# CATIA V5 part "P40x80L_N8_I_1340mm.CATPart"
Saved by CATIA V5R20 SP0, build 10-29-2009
Part number: 80x40_X-Traeger
Nomenclature: P40x80L_N8_I
Source: Unknown
Bounding box of the stored display mesh (mm): x -25.6 to 54.4, y 0 to 40, z 0 to 1420
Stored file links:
  C:\Users\Andi\Desktop\Offene Projekte\Plasmacutter\Rahmen\P40x80L_N8_I_1340mm.CATPart
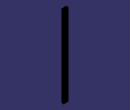
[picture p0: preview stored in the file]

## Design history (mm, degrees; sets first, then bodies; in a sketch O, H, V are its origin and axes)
Set1
  Sketch1 on face of Solid1, origin (0, 0, 1000), H (1, 0, 0), V (0, 1, 0)
    projected arc E1 centre (2, 37.5) radius 0.5 from (2, 38) to (1.5, 37.5) ccw from edge [face of Solid1 | face of Solid1]
    projected arc E2 centre (2, 35.5) radius 2.5 from (4.5, 35.5) to (2, 38) ccw from edge [face of Solid1 | face of Solid1]
    projected line E3 (4.5, 34.2924) -> (4.5, 35.5) from edge [face of Solid1 | face of Solid1]
    projected arc E4 centre (-0.5, 34.2924) radius 5 from (3.0355, 30.7569) to (4.5, 34.2924) ccw from edge [face of Solid1 | face of Solid1]
    projected line E5 (1.3431, 29.0645) -> (3.0355, 30.7569) from edge [face of Solid1 | face of Solid1]
    projected arc E6 centre (-2.1924, 32.6) radius 5 from (-2.1924, 27.6) to (1.3431, 29.0645) ccw from edge [face of Solid1 | face of Solid1]
    projected line E7 (-9.0076, 27.6) -> (-2.1924, 27.6) from edge [face of Solid1 | face of Solid1]
    projected arc E8 centre (-9.0076, 32.6) radius 5 from (-12.5431, 29.0645) to (-9.0076, 27.6) ccw from edge [face of Solid1 | face of Solid1]
    projected line E9 (-14.2355, 30.7569) -> (-12.5431, 29.0645) from edge [face of Solid1 | face of Solid1]
    projected arc E10 centre (-10.7, 34.2924) radius 5 from (-15.7, 34.2924) to (-14.2355, 30.7569) ccw from edge [face of Solid1 | face of Solid1]
    projected line E11 (-15.7, 35.5) -> (-15.7, 34.2924) from edge [face of Solid1 | face of Solid1]
    projected arc E12 centre (-13.2, 35.5) radius 2.5 from (-13.2, 38) to (-15.7, 35.5) ccw from edge [face of Solid1 | face of Solid1]
    projected arc E13 centre (-13.2, 37.5) radius 0.5 from (-12.7, 37.5) to (-13.2, 38) ccw from edge [face of Solid1 | face of Solid1]
    projected line E14 (-12.7, 35.85) -> (-12.7, 37.5) from edge [face of Solid1 | face of Solid1]
    projected arc E15 centre (-12.2, 35.85) radius 0.5 from (-12.7, 35.85) to (-12.2, 35.35) ccw from edge [face of Solid1 | face of Solid1]
    projected line E16 (-10.7, 35.35) -> (-12.2, 35.35) from edge [face of Solid1 | face of Solid1]
    projected arc E17 centre (-10.7, 36.35) radius 1 from (-10.7, 35.35) to (-9.7, 36.35) ccw from edge [face of Solid1 | face of Solid1]
    projected line E18 (-9.7, 38.5) -> (-9.7, 36.35) from edge [face of Solid1 | face of Solid1]
    projected arc E19 centre (-11.2, 38.5) radius 1.5 from (-9.7, 38.5) to (-11.2, 40) ccw from edge [face of Solid1 | face of Solid1]
    projected line E20 (-21.6, 40) -> (-11.2, 40) from edge [face of Solid1 | face of Solid1]
    projected arc E21 centre (-21.6, 36) radius 4 from (-21.6, 40) to (-25.6, 36) ccw from edge [face of Solid1 | face of Solid1]
    projected line E22 (-25.6, 25.6) -> (-25.6, 36) from edge [face of Solid1 | face of Solid1]
    projected arc E23 centre (-24.1, 25.6) radius 1.5 from (-25.6, 25.6) to (-24.1, 24.1) ccw from edge [face of Solid1 | face of Solid1]
    projected line E24 (-21.95, 24.1) -> (-24.1, 24.1) from edge [face of Solid1 | face of Solid1]
    projected arc E25 centre (-21.95, 25.1) radius 1 from (-21.95, 24.1) to (-20.95, 25.1) ccw from edge [face of Solid1 | face of Solid1]
    projected line E26 (-20.95, 26.6) -> (-20.95, 25.1) from edge [face of Solid1 | face of Solid1]
    projected arc E27 centre (-21.45, 26.6) radius 0.5 from (-20.95, 26.6) to (-21.45, 27.1) ccw from edge [face of Solid1 | face of Solid1]
    projected line E28 (-23.1, 27.1) -> (-21.45, 27.1) from edge [face of Solid1 | face of Solid1]
    projected arc E29 centre (-23.1, 27.6) radius 0.5 from (-23.6, 27.6) to (-23.1, 27.1) ccw from edge [face of Solid1 | face of Solid1]
    projected arc E30 centre (-21.1, 27.6) radius 2.5 from (-21.1, 30.1) to (-23.6, 27.6) ccw from edge [face of Solid1 | face of Solid1]
    projected line E31 (-19.8924, 30.1) -> (-21.1, 30.1) from edge [face of Solid1 | face of Solid1]
    projected arc E32 centre (-19.8924, 25.1) radius 5 from (-16.3569, 28.6355) to (-19.8924, 30.1) ccw from edge [face of Solid1 | face of Solid1]
    projected line E33 (-14.6645, 26.9431) -> (-16.3569, 28.6355) from edge [face of Solid1 | face of Solid1]
    projected arc E34 centre (-18.2, 23.4076) radius 5 from (-13.2, 23.4076) to (-14.6645, 26.9431) ccw from edge [face of Solid1 | face of Solid1]
    projected line E35 (-13.2, 16.5924) -> (-13.2, 23.4076) from edge [face of Solid1 | face of Solid1]
    projected arc E36 centre (-18.2, 16.5924) radius 5 from (-14.6645, 13.0569) to (-13.2, 16.5924) ccw from edge [face of Solid1 | face of Solid1]
    projected line E37 (-16.3569, 11.3645) -> (-14.6645, 13.0569) from edge [face of Solid1 | face of Solid1]
    projected arc E38 centre (-19.8924, 14.9) radius 5 from (-19.8924, 9.9) to (-16.3569, 11.3645) ccw from edge [face of Solid1 | face of Solid1]
    projected line E39 (-21.1, 9.9) -> (-19.8924, 9.9) from edge [face of Solid1 | face of Solid1]
    projected arc E40 centre (-21.1, 12.4) radius 2.5 from (-23.6, 12.4) to (-21.1, 9.9) ccw from edge [face of Solid1 | face of Solid1]
    projected arc E41 centre (-23.1, 12.4) radius 0.5 from (-23.1, 12.9) to (-23.6, 12.4) ccw from edge [face of Solid1 | face of Solid1]
    projected line E42 (-21.45, 12.9) -> (-23.1, 12.9) from edge [face of Solid1 | face of Solid1]
    projected arc E43 centre (-21.45, 13.4) radius 0.5 from (-21.45, 12.9) to (-20.95, 13.4) ccw from edge [face of Solid1 | face of Solid1]
    projected line E44 (-20.95, 14.9) -> (-20.95, 13.4) from edge [face of Solid1 | face of Solid1]
    projected arc E45 centre (-21.95, 14.9) radius 1 from (-20.95, 14.9) to (-21.95, 15.9) ccw from edge [face of Solid1 | face of Solid1]
    projected line E46 (-24.1, 15.9) -> (-21.95, 15.9) from edge [face of Solid1 | face of Solid1]
    projected arc E47 centre (-24.1, 14.4) radius 1.5 from (-24.1, 15.9) to (-25.6, 14.4) ccw from edge [face of Solid1 | face of Solid1]
    projected line E48 (-25.6, 4) -> (-25.6, 14.4) from edge [face of Solid1 | face of Solid1]
    projected arc E49 centre (-21.6, 4) radius 4 from (-25.6, 4) to (-21.6, 0) ccw from edge [face of Solid1 | face of Solid1]
    projected line E50 (-11.2, 0) -> (-21.6, 0) from edge [face of Solid1 | face of Solid1]
    projected arc E51 centre (-11.2, 1.5) radius 1.5 from (-11.2, 0) to (-9.7, 1.5) ccw from edge [face of Solid1 | face of Solid1]
    projected line E52 (-9.7, 3.65) -> (-9.7, 1.5) from edge [face of Solid1 | face of Solid1]
    projected arc E53 centre (-10.7, 3.65) radius 1 from (-9.7, 3.65) to (-10.7, 4.65) ccw from edge [face of Solid1 | face of Solid1]
    projected line E54 (-12.2, 4.65) -> (-10.7, 4.65) from edge [face of Solid1 | face of Solid1]
    projected arc E55 centre (-12.2, 4.15) radius 0.5 from (-12.2, 4.65) to (-12.7, 4.15) ccw from edge [face of Solid1 | face of Solid1]
    projected line E56 (-12.7, 2.5) -> (-12.7, 4.15) from edge [face of Solid1 | face of Solid1]
    projected arc E57 centre (-13.2, 2.5) radius 0.5 from (-13.2, 2) to (-12.7, 2.5) ccw from edge [face of Solid1 | face of Solid1]
    projected arc E58 centre (-13.2, 4.5) radius 2.5 from (-15.7, 4.5) to (-13.2, 2) ccw from edge [face of Solid1 | face of Solid1]
    projected line E59 (-15.7, 5.7076) -> (-15.7, 4.5) from edge [face of Solid1 | face of Solid1]
    projected arc E60 centre (-10.7, 5.7076) radius 5 from (-14.2355, 9.2431) to (-15.7, 5.7076) ccw from edge [face of Solid1 | face of Solid1]
    projected line E61 (-12.5431, 10.9355) -> (-14.2355, 9.2431) from edge [face of Solid1 | face of Solid1]
    projected arc E62 centre (-9.0076, 7.4) radius 5 from (-9.0076, 12.4) to (-12.5431, 10.9355) ccw from edge [face of Solid1 | face of Solid1]
    projected line E63 (-2.1924, 12.4) -> (-9.0076, 12.4) from edge [face of Solid1 | face of Solid1]
    projected arc E64 centre (-2.1924, 7.4) radius 5 from (1.3431, 10.9355) to (-2.1924, 12.4) ccw from edge [face of Solid1 | face of Solid1]
    projected line E65 (3.0355, 9.2431) -> (1.3431, 10.9355) from edge [face of Solid1 | face of Solid1]
    projected arc E66 centre (-0.5, 5.7076) radius 5 from (4.5, 5.7076) to (3.0355, 9.2431) ccw from edge [face of Solid1 | face of Solid1]
    projected line E67 (4.5, 4.5) -> (4.5, 5.7076) from edge [face of Solid1 | face of Solid1]
    projected arc E68 centre (2, 4.5) radius 2.5 from (2, 2) to (4.5, 4.5) ccw from edge [face of Solid1 | face of Solid1]
    projected arc E69 centre (2, 2.5) radius 0.5 from (1.5, 2.5) to (2, 2) ccw from edge [face of Solid1 | face of Solid1]
    projected line E70 (1.5, 4.15) -> (1.5, 2.5) from edge [face of Solid1 | face of Solid1]
    projected arc E71 centre (1, 4.15) radius 0.5 from (1.5, 4.15) to (1, 4.65) ccw from edge [face of Solid1 | face of Solid1]
    projected line E72 (-0.5, 4.65) -> (1, 4.65) from edge [face of Solid1 | face of Solid1]
    projected arc E73 centre (-0.5, 3.65) radius 1 from (-0.5, 4.65) to (-1.5, 3.65) ccw from edge [face of Solid1 | face of Solid1]
    projected line E74 (-1.5, 1.5) -> (-1.5, 3.65) from edge [face of Solid1 | face of Solid1]
    projected arc E75 centre (0, 1.5) radius 1.5 from (-1.5, 1.5) to (0, 0) ccw from edge [face of Solid1 | face of Solid1]
    projected line E76 (28.8, 0) -> (0, 0) from edge [face of Solid1 | face of Solid1]
    projected arc E77 centre (28.8, 1.5) radius 1.5 from (28.8, 0) to (30.3, 1.5) ccw from edge [face of Solid1 | face of Solid1]
    projected line E78 (30.3, 3.65) -> (30.3, 1.5) from edge [face of Solid1 | face of Solid1]
    projected arc E79 centre (29.3, 3.65) radius 1 from (30.3, 3.65) to (29.3, 4.65) ccw from edge [face of Solid1 | face of Solid1]
    projected line E80 (27.8, 4.65) -> (29.3, 4.65) from edge [face of Solid1 | face of Solid1]
    projected arc E81 centre (27.8, 4.15) radius 0.5 from (27.8, 4.65) to (27.3, 4.15) ccw from edge [face of Solid1 | face of Solid1]
    projected line E82 (27.3, 2.5) -> (27.3, 4.15) from edge [face of Solid1 | face of Solid1]
    projected arc E83 centre (26.8, 2.5) radius 0.5 from (26.8, 2) to (27.3, 2.5) ccw from edge [face of Solid1 | face of Solid1]
    projected arc E84 centre (26.8, 4.5) radius 2.5 from (24.3, 4.5) to (26.8, 2) ccw from edge [face of Solid1 | face of Solid1]
    projected line E85 (24.3, 5.7076) -> (24.3, 4.5) from edge [face of Solid1 | face of Solid1]
    projected arc E86 centre (29.3, 5.7076) radius 5 from (25.7645, 9.2431) to (24.3, 5.7076) ccw from edge [face of Solid1 | face of Solid1]
    projected line E87 (27.4569, 10.9355) -> (25.7645, 9.2431) from edge [face of Solid1 | face of Solid1]
    projected arc E88 centre (30.9924, 7.4) radius 5 from (30.9924, 12.4) to (27.4569, 10.9355) ccw from edge [face of Solid1 | face of Solid1]
    projected line E89 (37.8076, 12.4) -> (30.9924, 12.4) from edge [face of Solid1 | face of Solid1]
    projected arc E90 centre (37.8076, 7.4) radius 5 from (41.3431, 10.9355) to (37.8076, 12.4) ccw from edge [face of Solid1 | face of Solid1]
    projected line E91 (43.0355, 9.2431) -> (41.3431, 10.9355) from edge [face of Solid1 | face of Solid1]
    projected arc E92 centre (39.5, 5.7076) radius 5 from (44.5, 5.7076) to (43.0355, 9.2431) ccw from edge [face of Solid1 | face of Solid1]
    projected line E93 (44.5, 4.5) -> (44.5, 5.7076) from edge [face of Solid1 | face of Solid1]
    projected arc E94 centre (42, 4.5) radius 2.5 from (42, 2) to (44.5, 4.5) ccw from edge [face of Solid1 | face of Solid1]
    projected arc E95 centre (42, 2.5) radius 0.5 from (41.5, 2.5) to (42, 2) ccw from edge [face of Solid1 | face of Solid1]
    projected line E96 (41.5, 4.15) -> (41.5, 2.5) from edge [face of Solid1 | face of Solid1]
    projected arc E97 centre (41, 4.15) radius 0.5 from (41.5, 4.15) to (41, 4.65) ccw from edge [face of Solid1 | face of Solid1]
    projected line E98 (39.5, 4.65) -> (41, 4.65) from edge [face of Solid1 | face of Solid1]
    projected arc E99 centre (39.5, 3.65) radius 1 from (39.5, 4.65) to (38.5, 3.65) ccw from edge [face of Solid1 | face of Solid1]
    projected line E100 (38.5, 1.5) -> (38.5, 3.65) from edge [face of Solid1 | face of Solid1]
    projected arc E101 centre (40, 1.5) radius 1.5 from (38.5, 1.5) to (40, 0) ccw from edge [face of Solid1 | face of Solid1]
    projected line E102 (50.4, 0) -> (40, 0) from edge [face of Solid1 | face of Solid1]
    projected arc E103 centre (50.4, 4) radius 4 from (50.4, 0) to (54.4, 4) ccw from edge [face of Solid1 | face of Solid1]
    projected line E104 (54.4, 14.4) -> (54.4, 4) from edge [face of Solid1 | face of Solid1]
    projected arc E105 centre (52.9, 14.4) radius 1.5 from (54.4, 14.4) to (52.9, 15.9) ccw from edge [face of Solid1 | face of Solid1]
    projected line E106 (50.75, 15.9) -> (52.9, 15.9) from edge [face of Solid1 | face of Solid1]
    projected arc E107 centre (50.75, 14.9) radius 1 from (50.75, 15.9) to (49.75, 14.9) ccw from edge [face of Solid1 | face of Solid1]
    projected line E108 (49.75, 13.4) -> (49.75, 14.9) from edge [face of Solid1 | face of Solid1]
    projected arc E109 centre (50.25, 13.4) radius 0.5 from (49.75, 13.4) to (50.25, 12.9) ccw from edge [face of Solid1 | face of Solid1]
    projected line E110 (51.9, 12.9) -> (50.25, 12.9) from edge [face of Solid1 | face of Solid1]
    projected arc E111 centre (51.9, 12.4) radius 0.5 from (52.4, 12.4) to (51.9, 12.9) ccw from edge [face of Solid1 | face of Solid1]
    projected arc E112 centre (49.9, 12.4) radius 2.5 from (49.9, 9.9) to (52.4, 12.4) ccw from edge [face of Solid1 | face of Solid1]
    projected line E113 (48.6924, 9.9) -> (49.9, 9.9) from edge [face of Solid1 | face of Solid1]
    projected arc E114 centre (48.6924, 14.9) radius 5 from (45.1569, 11.3645) to (48.6924, 9.9) ccw from edge [face of Solid1 | face of Solid1]
    projected line E115 (43.4645, 13.0569) -> (45.1569, 11.3645) from edge [face of Solid1 | face of Solid1]
    projected arc E116 centre (47, 16.5924) radius 5 from (42, 16.5924) to (43.4645, 13.0569) ccw from edge [face of Solid1 | face of Solid1]
    projected line E117 (42, 23.4076) -> (42, 16.5924) from edge [face of Solid1 | face of Solid1]
    projected arc E118 centre (47, 23.4076) radius 5 from (43.4645, 26.9431) to (42, 23.4076) ccw from edge [face of Solid1 | face of Solid1]
    projected line E119 (45.1569, 28.6355) -> (43.4645, 26.9431) from edge [face of Solid1 | face of Solid1]
    projected arc E120 centre (48.6924, 25.1) radius 5 from (48.6924, 30.1) to (45.1569, 28.6355) ccw from edge [face of Solid1 | face of Solid1]
    projected line E121 (49.9, 30.1) -> (48.6924, 30.1) from edge [face of Solid1 | face of Solid1]
    projected arc E122 centre (49.9, 27.6) radius 2.5 from (52.4, 27.6) to (49.9, 30.1) ccw from edge [face of Solid1 | face of Solid1]
    projected arc E123 centre (51.9, 27.6) radius 0.5 from (51.9, 27.1) to (52.4, 27.6) ccw from edge [face of Solid1 | face of Solid1]
    projected line E124 (50.25, 27.1) -> (51.9, 27.1) from edge [face of Solid1 | face of Solid1]
    projected arc E125 centre (50.25, 26.6) radius 0.5 from (50.25, 27.1) to (49.75, 26.6) ccw from edge [face of Solid1 | face of Solid1]
    projected line E126 (49.75, 25.1) -> (49.75, 26.6) from edge [face of Solid1 | face of Solid1]
    projected arc E127 centre (50.75, 25.1) radius 1 from (49.75, 25.1) to (50.75, 24.1) ccw from edge [face of Solid1 | face of Solid1]
    projected line E128 (52.9, 24.1) -> (50.75, 24.1) from edge [face of Solid1 | face of Solid1]
    projected arc E129 centre (52.9, 25.6) radius 1.5 from (52.9, 24.1) to (54.4, 25.6) ccw from edge [face of Solid1 | face of Solid1]
    projected line E130 (54.4, 36) -> (54.4, 25.6) from edge [face of Solid1 | face of Solid1]
    projected arc E131 centre (50.4, 36) radius 4 from (54.4, 36) to (50.4, 40) ccw from edge [face of Solid1 | face of Solid1]
    projected line E132 (40, 40) -> (50.4, 40) from edge [face of Solid1 | face of Solid1]
    projected arc E133 centre (40, 38.5) radius 1.5 from (40, 40) to (38.5, 38.5) ccw from edge [face of Solid1 | face of Solid1]
    projected line E134 (38.5, 36.35) -> (38.5, 38.5) from edge [face of Solid1 | face of Solid1]
    projected arc E135 centre (39.5, 36.35) radius 1 from (38.5, 36.35) to (39.5, 35.35) ccw from edge [face of Solid1 | face of Solid1]
    projected line E136 (41, 35.35) -> (39.5, 35.35) from edge [face of Solid1 | face of Solid1]
    projected arc E137 centre (41, 35.85) radius 0.5 from (41, 35.35) to (41.5, 35.85) ccw from edge [face of Solid1 | face of Solid1]
    projected line E138 (41.5, 37.5) -> (41.5, 35.85) from edge [face of Solid1 | face of Solid1]
    projected arc E139 centre (42, 37.5) radius 0.5 from (42, 38) to (41.5, 37.5) ccw from edge [face of Solid1 | face of Solid1]
    projected arc E140 centre (42, 35.5) radius 2.5 from (44.5, 35.5) to (42, 38) ccw from edge [face of Solid1 | face of Solid1]
    projected line E141 (44.5, 34.2924) -> (44.5, 35.5) from edge [face of Solid1 | face of Solid1]
    projected arc E142 centre (39.5, 34.2924) radius 5 from (43.0355, 30.7569) to (44.5, 34.2924) ccw from edge [face of Solid1 | face of Solid1]
    projected line E143 (41.3431, 29.0645) -> (43.0355, 30.7569) from edge [face of Solid1 | face of Solid1]
    projected arc E144 centre (37.8076, 32.6) radius 5 from (37.8076, 27.6) to (41.3431, 29.0645) ccw from edge [face of Solid1 | face of Solid1]
    projected line E145 (30.9924, 27.6) -> (37.8076, 27.6) from edge [face of Solid1 | face of Solid1]
    projected arc E146 centre (30.9924, 32.6) radius 5 from (27.4569, 29.0645) to (30.9924, 27.6) ccw from edge [face of Solid1 | face of Solid1]
    projected line E147 (25.7645, 30.7569) -> (27.4569, 29.0645) from edge [face of Solid1 | face of Solid1]
    projected arc E148 centre (29.3, 34.2924) radius 5 from (24.3, 34.2924) to (25.7645, 30.7569) ccw from edge [face of Solid1 | face of Solid1]
    projected line E149 (24.3, 35.5) -> (24.3, 34.2924) from edge [face of Solid1 | face of Solid1]
    projected arc E150 centre (26.8, 35.5) radius 2.5 from (26.8, 38) to (24.3, 35.5) ccw from edge [face of Solid1 | face of Solid1]
    projected arc E151 centre (26.8, 37.5) radius 0.5 from (27.3, 37.5) to (26.8, 38) ccw from edge [face of Solid1 | face of Solid1]
    projected line E152 (27.3, 35.85) -> (27.3, 37.5) from edge [face of Solid1 | face of Solid1]
    projected arc E153 centre (27.8, 35.85) radius 0.5 from (27.3, 35.85) to (27.8, 35.35) ccw from edge [face of Solid1 | face of Solid1]
    projected line E154 (29.3, 35.35) -> (27.8, 35.35) from edge [face of Solid1 | face of Solid1]
    projected arc E155 centre (29.3, 36.35) radius 1 from (29.3, 35.35) to (30.3, 36.35) ccw from edge [face of Solid1 | face of Solid1]
    projected line E156 (30.3, 38.5) -> (30.3, 36.35) from edge [face of Solid1 | face of Solid1]
    projected arc E157 centre (28.8, 38.5) radius 1.5 from (30.3, 38.5) to (28.8, 40) ccw from edge [face of Solid1 | face of Solid1]
    projected line E158 (0, 40) -> (28.8, 40) from edge [face of Solid1 | face of Solid1]
    projected arc E159 centre (0, 38.5) radius 1.5 from (0, 40) to (-1.5, 38.5) ccw from edge [face of Solid1 | face of Solid1]
    projected line E160 (-1.5, 36.35) -> (-1.5, 38.5) from edge [face of Solid1 | face of Solid1]
    projected arc E161 centre (-0.5, 36.35) radius 1 from (-1.5, 36.35) to (-0.5, 35.35) ccw from edge [face of Solid1 | face of Solid1]
    projected line E162 (1, 35.35) -> (-0.5, 35.35) from edge [face of Solid1 | face of Solid1]
    projected arc E163 centre (1, 35.85) radius 0.5 from (1, 35.35) to (1.5, 35.85) ccw from edge [face of Solid1 | face of Solid1]
    projected line E164 (1.5, 37.5) -> (1.5, 35.85) from edge [face of Solid1 | face of Solid1]
    projected arc E165 centre (1.2, 8.2503) radius 5 from (6.2, 8.2503) to (4.7355, 11.7858) ccw from edge [face of Solid1 | face of Solid1]
    projected line E166 (4.7355, 11.7858) -> (3.6145, 12.9069) from edge [face of Solid1 | face of Solid1]
    projected arc E167 centre (7.15, 16.4424) radius 5 from (2.15, 16.4424) to (3.6145, 12.9069) ccw from edge [face of Solid1 | face of Solid1]
    projected line E168 (2.15, 16.4424) -> (2.15, 23.5576) from edge [face of Solid1 | face of Solid1]
    projected arc E169 centre (7.15, 23.5576) radius 5 from (3.6145, 27.0931) to (2.15, 23.5576) ccw from edge [face of Solid1 | face of Solid1]
    projected line E170 (3.6145, 27.0931) -> (4.7355, 28.2142) from edge [face of Solid1 | face of Solid1]
    projected arc E171 centre (1.2, 31.7497) radius 5 from (4.7355, 28.2142) to (6.2, 31.7497) ccw from edge [face of Solid1 | face of Solid1]
    projected line E172 (6.2, 31.7497) -> (6.2, 35.5) from edge [face of Solid1 | face of Solid1]
    projected arc E173 centre (8.7, 35.5) radius 2.5 from (8.7, 38) to (6.2, 35.5) ccw from edge [face of Solid1 | face of Solid1]
    projected line E174 (8.7, 38) -> (20.1, 38) from edge [face of Solid1 | face of Solid1]
    projected arc E175 centre (20.1, 35.5) radius 2.5 from (22.6, 35.5) to (20.1, 38) ccw from edge [face of Solid1 | face of Solid1]
    projected line E176 (22.6, 35.5) -> (22.6, 31.7497) from edge [face of Solid1 | face of Solid1]
    projected arc E177 centre (27.6, 31.7497) radius 5 from (22.6, 31.7497) to (24.0645, 28.2142) ccw from edge [face of Solid1 | face of Solid1]
    projected line E178 (24.0645, 28.2142) -> (25.1855, 27.0931) from edge [face of Solid1 | face of Solid1]
    projected arc E179 centre (21.65, 23.5576) radius 5 from (26.65, 23.5576) to (25.1855, 27.0931) ccw from edge [face of Solid1 | face of Solid1]
    projected line E180 (26.65, 23.5576) -> (26.65, 16.4424) from edge [face of Solid1 | face of Solid1]
    projected arc E181 centre (21.65, 16.4424) radius 5 from (25.1855, 12.9069) to (26.65, 16.4424) ccw from edge [face of Solid1 | face of Solid1]
    projected line E182 (25.1855, 12.9069) -> (24.0645, 11.7858) from edge [face of Solid1 | face of Solid1]
    projected arc E183 centre (27.6, 8.2503) radius 5 from (24.0645, 11.7858) to (22.6, 8.2503) ccw from edge [face of Solid1 | face of Solid1]
    projected line E184 (22.6, 8.2503) -> (22.6, 4.5) from edge [face of Solid1 | face of Solid1]
    projected arc E185 centre (20.1, 4.5) radius 2.5 from (20.1, 2) to (22.6, 4.5) ccw from edge [face of Solid1 | face of Solid1]
    projected line E186 (20.1, 2) -> (8.7, 2) from edge [face of Solid1 | face of Solid1]
    projected arc E187 centre (8.7, 4.5) radius 2.5 from (6.2, 4.5) to (8.7, 2) ccw from edge [face of Solid1 | face of Solid1]
    projected line E188 (6.2, 4.5) -> (6.2, 8.2503) from edge [face of Solid1 | face of Solid1]
    projected arc E189 centre (-23.3, 7.7) radius 0.5 from (-23.3, 8.2) to (-23.8, 7.7) ccw from edge [face of Solid1 | face of Solid1]
    projected line E190 (-23.3, 8.2) -> (-17.9, 8.2) from edge [face of Solid1 | face of Solid1]
    projected arc E191 centre (-17.9, 7.7) radius 0.5 from (-17.4, 7.7) to (-17.9, 8.2) ccw from edge [face of Solid1 | face of Solid1]
    projected line E192 (-17.4, 7.7) -> (-17.4, 2.3) from edge [face of Solid1 | face of Solid1]
    projected arc E193 centre (-17.9, 2.3) radius 0.5 from (-17.9, 1.8) to (-17.4, 2.3) ccw from edge [face of Solid1 | face of Solid1]
    projected line E194 (-17.9, 1.8) -> (-21.6, 1.8) from edge [face of Solid1 | face of Solid1]
    projected arc E195 centre (-21.6, 4) radius 2.2 from (-23.8, 4) to (-21.6, 1.8) ccw from edge [face of Solid1 | face of Solid1]
    projected line E196 (-23.8, 4) -> (-23.8, 7.7) from edge [face of Solid1 | face of Solid1]
    projected arc E197 centre (-17.9, 37.7) radius 0.5 from (-17.4, 37.7) to (-17.9, 38.2) ccw from edge [face of Solid1 | face of Solid1]
    projected line E198 (-17.4, 37.7) -> (-17.4, 32.3) from edge [face of Solid1 | face of Solid1]
    projected arc E199 centre (-17.9, 32.3) radius 0.5 from (-17.9, 31.8) to (-17.4, 32.3) ccw from edge [face of Solid1 | face of Solid1]
    projected line E200 (-17.9, 31.8) -> (-23.3, 31.8) from edge [face of Solid1 | face of Solid1]
    projected arc E201 centre (-23.3, 32.3) radius 0.5 from (-23.8, 32.3) to (-23.3, 31.8) ccw from edge [face of Solid1 | face of Solid1]
    projected line E202 (-23.8, 32.3) -> (-23.8, 36) from edge [face of Solid1 | face of Solid1]
    projected arc E203 centre (-21.6, 36) radius 2.2 from (-21.6, 38.2) to (-23.8, 36) ccw from edge [face of Solid1 | face of Solid1]
    projected line E204 (-21.6, 38.2) -> (-17.9, 38.2) from edge [face of Solid1 | face of Solid1]
    projected arc E205 centre (52.1, 7.7) radius 0.5 from (52.6, 7.7) to (52.1, 8.2) ccw from edge [face of Solid1 | face of Solid1]
    projected line E206 (52.6, 7.7) -> (52.6, 4) from edge [face of Solid1 | face of Solid1]
    projected arc E207 centre (50.4, 4) radius 2.2 from (50.4, 1.8) to (52.6, 4) ccw from edge [face of Solid1 | face of Solid1]
    projected line E208 (50.4, 1.8) -> (46.7, 1.8) from edge [face of Solid1 | face of Solid1]
    projected arc E209 centre (46.7, 2.3) radius 0.5 from (46.2, 2.3) to (46.7, 1.8) ccw from edge [face of Solid1 | face of Solid1]
    projected line E210 (46.2, 2.3) -> (46.2, 7.7) from edge [face of Solid1 | face of Solid1]
    projected arc E211 centre (46.7, 7.7) radius 0.5 from (46.7, 8.2) to (46.2, 7.7) ccw from edge [face of Solid1 | face of Solid1]
    projected line E212 (46.7, 8.2) -> (52.1, 8.2) from edge [face of Solid1 | face of Solid1]
    projected arc E213 centre (46.7, 37.7) radius 0.5 from (46.7, 38.2) to (46.2, 37.7) ccw from edge [face of Solid1 | face of Solid1]
    projected line E214 (46.7, 38.2) -> (50.4, 38.2) from edge [face of Solid1 | face of Solid1]
    projected arc E215 centre (50.4, 36) radius 2.2 from (52.6, 36) to (50.4, 38.2) ccw from edge [face of Solid1 | face of Solid1]
    projected line E216 (52.6, 36) -> (52.6, 32.3) from edge [face of Solid1 | face of Solid1]
    projected arc E217 centre (52.1, 32.3) radius 0.5 from (52.1, 31.8) to (52.6, 32.3) ccw from edge [face of Solid1 | face of Solid1]
    projected line E218 (52.1, 31.8) -> (46.7, 31.8) from edge [face of Solid1 | face of Solid1]
    projected arc E219 centre (46.7, 32.3) radius 0.5 from (46.2, 32.3) to (46.7, 31.8) ccw from edge [face of Solid1 | face of Solid1]
    projected line E220 (46.2, 32.3) -> (46.2, 37.7) from edge [face of Solid1 | face of Solid1]
    projected arc E221 centre (34.4, 20) radius 3.35 from (31.05, 20) to (37.75, 20) ccw from edge [face of Solid1 | face of Solid1]
    projected arc E222 centre (34.4, 20) radius 3.35 from (37.75, 20) to (31.05, 20) ccw from edge [face of Solid1 | face of Solid1]
    projected arc E223 centre (-5.6, 20) radius 3.35 from (-8.95, 20) to (-2.25, 20) ccw from edge [face of Solid1 | face of Solid1]
    projected arc E224 centre (-5.6, 20) radius 3.35 from (-2.25, 20) to (-8.95, 20) ccw from edge [face of Solid1 | face of Solid1]
Body1 "MANIFOLD_SOLID_BREP #7665" (main body)
  Solid1: solid without history
  Pad1: profile Sketch1, direction (0, 0, 1), length 420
